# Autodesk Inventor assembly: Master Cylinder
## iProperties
Length Units: 11269
Angle Units: 11279
Time Units: 11290
Mass Units: 11283
Shininess: 3
Angle Display Precision: 2
Document Length Units: 11269
Document Angle Units: 11279
Document Time Units: 11290
Document Mass Units: 11283
Document Length Units Precision: 3
Document Angle Units Precision: 2
Compacted: True
Created: 2001-08
Part Number: Master Cylinder
Document SubType Name: Assembly
Designer: Martin Budgell
Density: 0.0
Volumn: 0.0
Area: 0.0
PropertySet Name: Model Information
Control State: 0
Master: False
Checked Out: False
Author: Martin Budgell
